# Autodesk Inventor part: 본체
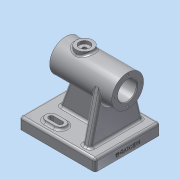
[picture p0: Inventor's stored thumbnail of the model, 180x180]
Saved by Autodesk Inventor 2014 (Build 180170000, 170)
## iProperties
Created: 2026-09
Part Number: 본체
Material: 알루미늄 6061
Document SubType Name: Modeling
Designer: dg
Density: 2.71 g/cm^3
Appearance: 알루미늄 - 평지
Mass: 635.444 g
Surface Area: 512.685 cm^2
Volume: 234.481 cm^3
Author: dg
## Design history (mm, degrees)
sketch "스케치1"
  geometry: L1 (-50, -43)-(50, -43); L2 (50, -43)-(50, 43); L3 (50, 43)-(-50, 43); L4 (-50, 43)-(-50, -43); L5 (-50, -43)-(50, 43); L6 (50, -43)-(-50, 43); 1 further point
  constraints: 12 end point, 2 midpoint, 2 parallel, 1 horizontal, 1 perpendicular
  dimensions: "d0" = 100 distance of L1.start L1.end; "d1" = 86 distance of L1.end L2.end
extrude "돌출1" new body sketch "스케치1" distance "d2" = 15; taper "d3" = 0 deg
node "작업 평면1"
sketch "스케치2"
  geometry: L1 (32, 21)-(-50, 21); L2 (-50, 21)-(-50, 0); L3 (-50, 0)-(32, 0); L4 (32, 0)-(32, 21); 2 further points
  constraints: 8 end point, 2 parallel, 1 horizontal, 1 horizontal alignment, 1 perpendicular, 1 vertical alignment
  dimensions: "d5" = 82 distance of L1.start L1.end; "d6" = 21 distance between parallel lines of L3 L1
revolve "회전1" sketch "스케치2" stored, may be unused: angle "d7" = 90 deg
node "작업 평면2"
sketch "스케치3"
  geometry: L1 (0, 0)-(-15, 0) reference; L2 (-15, 0)-(-15, 86) reference; L3 (-15, 86)-(0, 86) reference; L4 (0, 86)-(0, 0) reference; L5 (-76.814, 22.559)-(-15, 8); L6 (-76.814, 63.441)-(-15, 78); A1 r 21 centre (-72, 43) between (-76.814, 22.559) and (-76.814, 63.441) reference; 1 further point
  constraints: 4 end point, 2 point on circle, 2 point on line, 2 tangent
  dimensions: "d9" = 8 distance of L1.end L5.end; "d10" = 8 distance of L2.end L6.end
extrude "돌출2" join sketch "스케치3" distance "d11" = 10; taper "d12" = 0 deg
sketch "스케치4"
  geometry: L1 (-50, 0)-(-50, 15) reference; L2 (-50, 15)-(-35, 15) reference; L3 (-25, 51)-(-25, 15) reference; L4 (-35, 51)-(-50, 51) reference; L5 (-50, 51)-(-50, 93) reference; L6 (-50, 93)-(32, 93) reference; L7 (32, 93)-(32, 51) reference; L8 (32, 51)-(-25, 51) reference; L9 (-35, 15)-(-35, 51) reference; L10 (-25, 15)-(50, 15) reference; L11 (50, 15)-(50, 0) reference; L12 (50, 0)-(-50, 0) reference; L13 (35, 15)-(16.801, 65); L14 (16.801, 65)-(-30, 65); L15 (-30, 65)-(-30, 15); L16 (-30, 15)-(35, 15); 1 further point
  constraints: 8 end point, 2 parallel, 1 perpendicular, 1 point on line
  dimensions: "d13" = 70 deg angle of L10 L13; "d14" = 15 distance of L10.end L13.start; "d15" = 65 distance from line of L13.start L15; "d16" = 50 distance between parallel lines of L10 L14
extrude "돌출3" join sketch "스케치4" stored distance "d17" = 10; taper "d18" = 0 deg
hole "구멍1" diameter "d21" = 25; stored, may be unused: countersink angle "d25" = 90 deg, drill point angle "d27" = 118 deg; dims "d19" = 10, "d20" = 10, "d22" = 6, "d23" = 29, "d24" = 62, "d26" = 200
node "작업 평면3"
sketch "스케치5"
  geometry: L1 (32, -21)-(32, 21) reference; C1 r 11 at (7, 0); 1 further point
  constraints: 1 centre point, 1 horizontal alignment
  dimensions: "d29" = 22 diameter of C1; "d30" = 25 distance from line of L1 C1.centre
extrude "돌출4" join sketch "스케치5" stored distance "d31" = 10; taper "d32" = 0 deg
hole "구멍2" diameter "d35" = 4.917; stored, may be unused: countersink angle "d39" = 90 deg, drill point angle "d41" = 118 deg; dims "d33" = 10, "d34" = 10, "d36" = 6, "d37" = 14, "d38" = 4, "d40" = 20
sketch "스케치6"
  geometry: L1 (-50, 43)-(-50, -43) reference; L2 (-24, -27)-(-12, -27); L3 (-24, -34)-(-12, -34); L4 (-12, -20)-(-24, -20); A1 r 7 centre (-24, -27) between (-24, -20) and (-24, -34); A2 r 7 centre (-12, -27) between (-12, -34) and (-12, -20); 2 further points
  constraints: 8 end point, 4 point on circle, 4 tangent, 2 centre point, 1 midpoint, 1 parallel, 1 perpendicular
  dimensions: "d42" = 26 distance from line of L1 L2.start; "d43" = 12 distance of L2.end L2.start; "d44" = 14 distance of L3.start L4.end; "d45" = 27 vertical distance of point (0, 0) point (-18, -27)
extrude "돌출5" join sketch "스케치6" distance "d46" = 3; taper "d47" = 0 deg
sketch "스케치7"
  geometry: L1 (-24, -34)-(-12, -34) reference; L2 (-24, -27)-(-12, -27); L3 (-24, -23.7)-(-12, -23.7); L4 (-12, -30.3)-(-24, -30.3); A1 r 7 centre (-12, -27) between (-12, -34) and (-12, -20) reference; A2 r 7 centre (-24, -27) between (-24, -20) and (-24, -34) reference; A3 r 3.3 centre (-24, -27) between (-24, -23.7) and (-24, -30.3); A4 r 3.3 centre (-12, -27) between (-12, -30.3) and (-12, -23.7); 2 further points
  constraints: 8 end point, 4 point on circle, 4 tangent, 2 centre point, 2 parallel, 1 midpoint
  dimensions: "d48" = 6.6 distance of L4.end L3.start
extrude "돌출6" cut sketch "스케치7" stored distance "d49" = 3; taper "d50" = 0 deg
sketch "스케치8"
  geometry: C1 r 14.5 at (0, 0) reference; 2 further points
  constraints: 1 horizontal alignment
  dimensions: "d51" = 18 distance of C1.centre point (18, 0)
hole "구멍3" sketch "스케치8" at (18, 0) diameter "d52" = 2.459; stored, may be unused: countersink angle "d56" = 90 deg, drill point angle "d58" = 118 deg; dims "d53" = 8, "d54" = 14, "d55" = 4, "d57" = 10
node "작업 평면4"
fillet "모깎기1" dims "d62" = 3
fillet "모깎기3" dims "d64" = 3
fillet "모깎기4" dims "d65" = 3
chamfer "모따기1" distance "d67" = 1; stored, may be unused: second distance "d68" = 2, angle "d69" = 45 deg
sketch "스케치9"
  geometry: L1 (0, 0)-(0, 80) reference; 3 further points
  constraints: 1 horizontal alignment, 1 midpoint, 1 other
  dimensions: "d70" = 6 distance from line of L1 point (-6, 40)
feature "엠보싱1" sketch "스케치9" dims "d0" = 100, "d1" = 86, "d71" = 0.5, "d72" = 0
fillet "모깎기7" dims "d74" = 3
fillet "모깎기8" dims "d75" = 3
node "솔리드1"
mirror "대칭1"
pattern_circular "원형 패턴1" dims angle "d60" = 360 deg
mirror "대칭2"
node "절단 모서리 투영1"
node "절단 모서리 투영2"
other parameters: "d4" = -72, "d8" = -15, "d28" = -96
